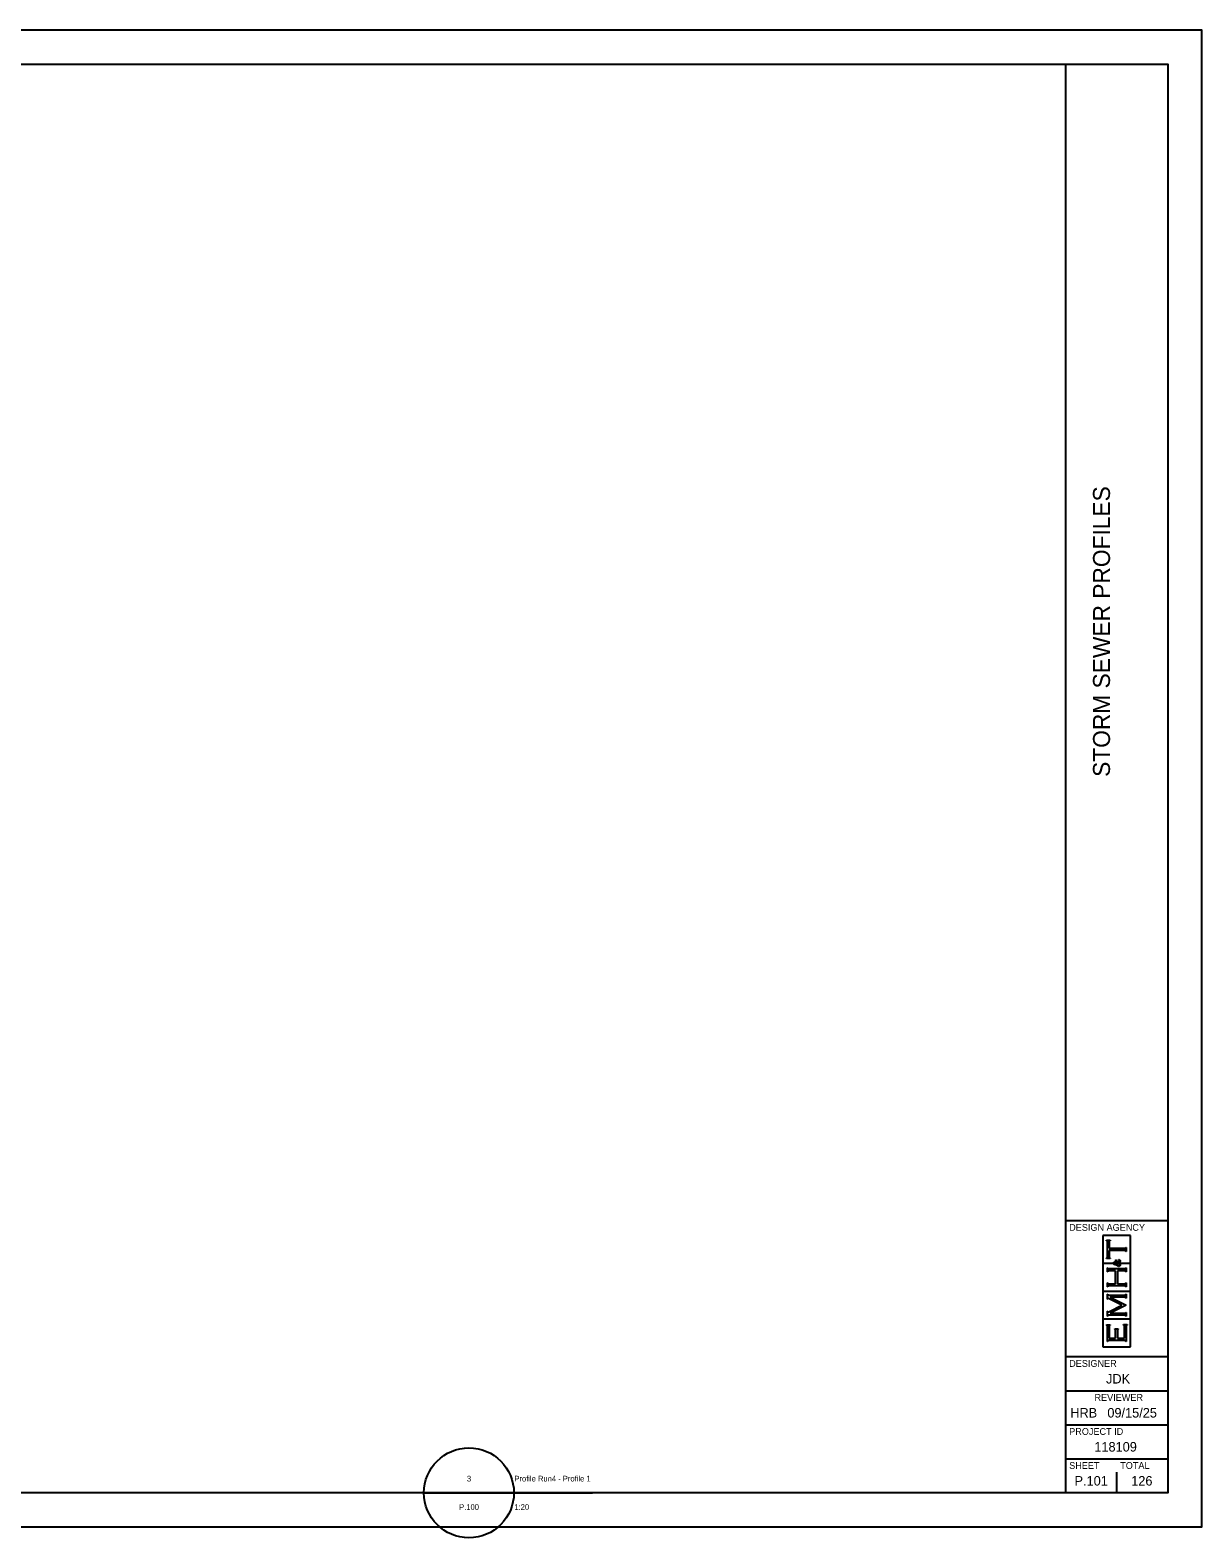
# Model space of a CAD drawing. Extents: x -0.4 to 34, y -0.2 to 22.
# Drawn here: x 16.78 to 34, y -0.16 to 22 of the extents above; entities that cross this region are included whole.
import ezdxf

# ---------------------------------------------------------------- set-up
doc = ezdxf.new("R2010")
doc.units = 0
for name, color, linetype in [('_CIVIL_CONSTRUCTION', 7, 'Continuous'), ('GE_P_Alignment', 7, 'Continuous'), ('PF_X_Ground_Line', 7, 'Continuous'), ('SC_Scratch1', 7, 'Continuous')]:
    doc.layers.add(name, color=color, linetype=linetype)

msp = doc.modelspace()

# ---------------------------------------------------------------- linework, layer by layer
at = {"layer": '_CIVIL_CONSTRUCTION'}
for p, q in [((32, 0.5), (32, 21.5)), ((32, 4.5), (33.5, 4.5)), ((32, 2.5), (33.5, 2.5)), ((32, 2), (33.5, 2)), ((32, 1.5), (33.5, 1.5)), ((32, 1), (33.5, 1))]:
    msp.add_line(p, q, dxfattribs=at)
msp.add_lwpolyline([(1.5, 21.5), (33.5, 21.5), (33.5, 0.5), (1.5, 0.5)], close=True, dxfattribs=at)
at = {"layer": 'GE_P_Alignment'}
msp.add_lwpolyline([(0, 0), (34, 0), (34, 22), (0, 22)], close=True, dxfattribs=at)
at = {"layer": 'PF_X_Ground_Line'}
for p, q in [((32.952, 4.279), (32.547, 4.279)), ((32.547, 4.279), (32.547, 3.875)), ((32.952, 3.875), (32.952, 4.279)), ((32.598, 4.204), (32.598, 4.211)), ((32.598, 4.211), (32.65, 4.211)), ((32.603, 4.203), (32.598, 4.204)), ((32.606, 4.201), (32.603, 4.203)), ((32.608, 4.199), (32.606, 4.201)), ((32.61, 4.196), (32.608, 4.199)), ((32.611, 4.192), (32.61, 4.196)), ((32.611, 4.187), (32.611, 4.192)), ((32.611, 3.968), (32.611, 4.187)), ((32.638, 4.196), (32.637, 4.192)), ((32.637, 4.192), (32.637, 4.187)), ((32.637, 4.187), (32.637, 4.093)), ((32.637, 4.093), (32.864, 4.093)), ((32.864, 4.061), (32.637, 4.061)), ((32.637, 4.061), (32.637, 3.968)), ((32.64, 4.199), (32.638, 4.196)), ((32.642, 4.201), (32.64, 4.199)), ((32.645, 4.203), (32.642, 4.201)), ((32.65, 4.204), (32.645, 4.203)), ((32.65, 4.211), (32.65, 4.204)), ((32.864, 4.093), (32.869, 4.093)), ((32.87, 4.061), (32.864, 4.061)), ((32.869, 4.093), (32.873, 4.094)), ((32.874, 4.06), (32.87, 4.061)), ((32.873, 4.094), (32.876, 4.096)), ((32.876, 4.059), (32.874, 4.06)), ((32.876, 4.096), (32.878, 4.097)), ((32.878, 4.057), (32.876, 4.059)), ((32.878, 4.097), (32.88, 4.101)), ((32.88, 4.053), (32.878, 4.057)), ((32.88, 4.101), (32.881, 4.106)), ((32.881, 4.048), (32.88, 4.053)), ((32.881, 4.106), (32.888, 4.106)), ((32.888, 4.048), (32.881, 4.048)), ((32.888, 4.106), (32.888, 4.048)), ((32.547, 3.875), (32.696, 3.875)), ((32.696, 3.869), (32.547, 3.869)), ((32.547, 3.869), (32.547, 3.465)), ((32.598, 3.95), (32.603, 3.951)), ((32.598, 3.944), (32.598, 3.95)), ((32.65, 3.944), (32.598, 3.944)), ((32.603, 3.951), (32.606, 3.953)), ((32.606, 3.953), (32.608, 3.955)), ((32.608, 3.955), (32.61, 3.958)), ((32.61, 3.958), (32.611, 3.962)), ((32.611, 3.962), (32.611, 3.968)), ((32.611, 3.749), (32.611, 3.807)), ((32.611, 3.807), (32.617, 3.807)), ((32.617, 3.807), (32.619, 3.802)), ((32.619, 3.802), (32.62, 3.798)), ((32.62, 3.798), (32.623, 3.797)), ((32.623, 3.797), (32.625, 3.795)), ((32.625, 3.795), (32.629, 3.794)), ((32.629, 3.794), (32.635, 3.794)), ((32.635, 3.794), (32.864, 3.794)), ((32.637, 3.968), (32.637, 3.962)), ((32.637, 3.962), (32.638, 3.958)), ((32.638, 3.958), (32.64, 3.955)), ((32.64, 3.955), (32.642, 3.953)), ((32.642, 3.953), (32.645, 3.951)), ((32.645, 3.951), (32.65, 3.95)), ((32.65, 3.95), (32.65, 3.944)), ((32.696, 3.875), (32.696, 3.869)), ((32.703, 3.879), (32.705, 3.883)), ((32.703, 3.873), (32.703, 3.879)), ((32.703, 3.868), (32.703, 3.873)), ((32.705, 3.863), (32.703, 3.868)), ((32.705, 3.883), (32.708, 3.887)), ((32.708, 3.858), (32.705, 3.863)), ((32.708, 3.887), (32.711, 3.89)), ((32.709, 3.879), (32.708, 3.876)), ((32.708, 3.876), (32.708, 3.873)), ((32.708, 3.873), (32.708, 3.869)), ((32.708, 3.869), (32.71, 3.866)), ((32.712, 3.853), (32.708, 3.858)), ((32.712, 3.881), (32.709, 3.879)), ((32.71, 3.866), (32.712, 3.864)), ((32.711, 3.89), (32.715, 3.892)), ((32.714, 3.883), (32.712, 3.881)), ((32.712, 3.864), (32.715, 3.862)), ((32.718, 3.85), (32.712, 3.853)), ((32.716, 3.884), (32.714, 3.883)), ((32.715, 3.892), (32.72, 3.892)), ((32.715, 3.862), (32.718, 3.861)), ((32.72, 3.884), (32.716, 3.884)), ((32.718, 3.861), (32.721, 3.861)), ((32.726, 3.85), (32.718, 3.85)), ((32.72, 3.892), (32.725, 3.892)), ((32.724, 3.884), (32.72, 3.884)), ((32.721, 3.861), (32.723, 3.861)), ((32.723, 3.861), (32.725, 3.862)), ((32.728, 3.882), (32.724, 3.884)), ((32.725, 3.892), (32.729, 3.89)), ((32.725, 3.862), (32.728, 3.862)), ((32.729, 3.85), (32.726, 3.85)), ((32.731, 3.88), (32.728, 3.882)), ((32.728, 3.862), (32.731, 3.863)), ((32.729, 3.89), (32.732, 3.887)), ((32.731, 3.85), (32.729, 3.85)), ((32.734, 3.877), (32.731, 3.88)), ((32.731, 3.863), (32.735, 3.865)), ((32.734, 3.851), (32.731, 3.85)), ((32.732, 3.887), (32.736, 3.883)), ((32.737, 3.872), (32.734, 3.877)), ((32.737, 3.852), (32.734, 3.851)), ((32.735, 3.865), (32.74, 3.867)), ((32.736, 3.883), (32.74, 3.878)), ((32.74, 3.867), (32.737, 3.872)), ((32.741, 3.853), (32.737, 3.852)), ((32.738, 3.893), (32.738, 3.922)), ((32.738, 3.922), (32.741, 3.922)), ((32.741, 3.893), (32.738, 3.893)), ((32.74, 3.878), (32.744, 3.869)), ((32.741, 3.922), (32.741, 3.918)), ((32.741, 3.918), (32.742, 3.915)), ((32.742, 3.896), (32.741, 3.895)), ((32.741, 3.895), (32.741, 3.893)), ((32.746, 3.855), (32.741, 3.853)), ((32.742, 3.915), (32.743, 3.913)), ((32.743, 3.897), (32.742, 3.896)), ((32.743, 3.913), (32.745, 3.911)), ((32.745, 3.899), (32.743, 3.897)), ((32.744, 3.869), (32.754, 3.875)), ((32.745, 3.911), (32.749, 3.908)), ((32.746, 3.899), (32.745, 3.899)), ((32.748, 3.899), (32.746, 3.899)), ((32.752, 3.844), (32.746, 3.855)), ((32.755, 3.899), (32.748, 3.899)), ((32.749, 3.908), (32.756, 3.904)), ((32.756, 3.86), (32.751, 3.857)), ((32.751, 3.857), (32.754, 3.852)), ((32.757, 3.837), (32.752, 3.844)), ((32.754, 3.875), (32.764, 3.881)), ((32.754, 3.852), (32.757, 3.848)), ((32.763, 3.895), (32.755, 3.899)), ((32.756, 3.904), (32.763, 3.9)), ((32.761, 3.863), (32.756, 3.86)), ((32.757, 3.848), (32.761, 3.845)), ((32.763, 3.833), (32.757, 3.837)), ((32.764, 3.865), (32.761, 3.863)), ((32.761, 3.845), (32.765, 3.843)), ((32.763, 3.9), (32.77, 3.896)), ((32.772, 3.887), (32.763, 3.895)), ((32.768, 3.829), (32.763, 3.833)), ((32.764, 3.881), (32.772, 3.887)), ((32.768, 3.867), (32.764, 3.865)), ((32.765, 3.843), (32.769, 3.841)), ((32.774, 3.872), (32.768, 3.867)), ((32.774, 3.827), (32.768, 3.829)), ((32.769, 3.841), (32.773, 3.841)), ((32.77, 3.896), (32.776, 3.891)), ((32.773, 3.841), (32.778, 3.841)), ((32.782, 3.878), (32.774, 3.872)), ((32.779, 3.827), (32.774, 3.827)), ((32.776, 3.891), (32.781, 3.895)), ((32.778, 3.841), (32.782, 3.843)), ((32.779, 3.923), (32.781, 3.926)), ((32.782, 3.922), (32.779, 3.923)), ((32.785, 3.827), (32.779, 3.827)), ((32.781, 3.926), (32.787, 3.924)), ((32.781, 3.895), (32.784, 3.898)), ((32.785, 3.921), (32.782, 3.922)), ((32.786, 3.873), (32.782, 3.878)), ((32.782, 3.843), (32.786, 3.846)), ((32.784, 3.898), (32.786, 3.901)), ((32.786, 3.919), (32.785, 3.921)), ((32.79, 3.829), (32.785, 3.827)), ((32.788, 3.917), (32.786, 3.919)), ((32.786, 3.901), (32.788, 3.904)), ((32.791, 3.886), (32.786, 3.881)), ((32.786, 3.881), (32.791, 3.876)), ((32.788, 3.869), (32.786, 3.873)), ((32.786, 3.846), (32.789, 3.849)), ((32.787, 3.924), (32.792, 3.921)), ((32.789, 3.914), (32.788, 3.917)), ((32.788, 3.904), (32.789, 3.908)), ((32.79, 3.867), (32.788, 3.869)), ((32.789, 3.911), (32.789, 3.914)), ((32.789, 3.908), (32.789, 3.911)), ((32.789, 3.849), (32.791, 3.853)), ((32.791, 3.864), (32.79, 3.867)), ((32.793, 3.834), (32.79, 3.829)), ((32.794, 3.89), (32.791, 3.886)), ((32.791, 3.876), (32.795, 3.87)), ((32.791, 3.861), (32.791, 3.864)), ((32.791, 3.859), (32.791, 3.861)), ((32.791, 3.853), (32.791, 3.859)), ((32.792, 3.921), (32.795, 3.918)), ((32.797, 3.838), (32.793, 3.834)), ((32.796, 3.894), (32.794, 3.89)), ((32.795, 3.918), (32.798, 3.914)), ((32.795, 3.87), (32.797, 3.866)), ((32.798, 3.897), (32.796, 3.894)), ((32.797, 3.866), (32.798, 3.861)), ((32.799, 3.844), (32.797, 3.838)), ((32.798, 3.914), (32.799, 3.91)), ((32.799, 3.901), (32.798, 3.897)), ((32.798, 3.861), (32.799, 3.857)), ((32.799, 3.91), (32.799, 3.905)), ((32.799, 3.905), (32.799, 3.901)), ((32.803, 3.869), (32.799, 3.875)), ((32.799, 3.875), (32.952, 3.875)), ((32.799, 3.857), (32.799, 3.852)), ((32.799, 3.852), (32.799, 3.844)), ((32.952, 3.869), (32.803, 3.869)), ((32.864, 3.794), (32.869, 3.794)), ((32.869, 3.794), (32.873, 3.795)), ((32.873, 3.795), (32.876, 3.797)), ((32.876, 3.797), (32.878, 3.798)), ((32.878, 3.798), (32.88, 3.802)), ((32.88, 3.802), (32.881, 3.807)), ((32.881, 3.807), (32.888, 3.807)), ((32.888, 3.807), (32.888, 3.749)), ((32.952, 3.465), (32.952, 3.869)), ((32.617, 3.749), (32.611, 3.749)), ((32.611, 3.527), (32.611, 3.585)), ((32.611, 3.585), (32.617, 3.585)), ((32.618, 3.754), (32.617, 3.749)), ((32.617, 3.585), (32.619, 3.58)), ((32.62, 3.758), (32.618, 3.754)), ((32.619, 3.58), (32.62, 3.576)), ((32.623, 3.76), (32.62, 3.758)), ((32.62, 3.576), (32.623, 3.574)), ((32.625, 3.761), (32.623, 3.76)), ((32.623, 3.574), (32.625, 3.573)), ((32.629, 3.762), (32.625, 3.761)), ((32.625, 3.573), (32.629, 3.572)), ((32.635, 3.762), (32.629, 3.762)), ((32.629, 3.572), (32.635, 3.572)), ((32.732, 3.762), (32.635, 3.762)), ((32.635, 3.572), (32.732, 3.572)), ((32.732, 3.572), (32.732, 3.762)), ((32.864, 3.762), (32.759, 3.762)), ((32.759, 3.762), (32.759, 3.572)), ((32.759, 3.572), (32.864, 3.572)), ((32.87, 3.762), (32.864, 3.762)), ((32.864, 3.572), (32.87, 3.572)), ((32.874, 3.761), (32.87, 3.762)), ((32.87, 3.572), (32.874, 3.573)), ((32.876, 3.76), (32.874, 3.761)), ((32.874, 3.573), (32.876, 3.574)), ((32.878, 3.758), (32.876, 3.76)), ((32.876, 3.574), (32.878, 3.576)), ((32.88, 3.754), (32.878, 3.758)), ((32.878, 3.576), (32.88, 3.58)), ((32.881, 3.749), (32.88, 3.754)), ((32.88, 3.58), (32.881, 3.585)), ((32.888, 3.749), (32.881, 3.749)), ((32.881, 3.585), (32.888, 3.585)), ((32.888, 3.585), (32.888, 3.527)), ((32.547, 3.465), (32.952, 3.465)), ((32.952, 3.459), (32.547, 3.459)), ((32.547, 3.459), (32.547, 3.055)), ((32.617, 3.527), (32.611, 3.527)), ((32.611, 3.345), (32.611, 3.418)), ((32.611, 3.418), (32.617, 3.418)), ((32.617, 3.345), (32.611, 3.345)), ((32.618, 3.532), (32.617, 3.527)), ((32.617, 3.418), (32.619, 3.412)), ((32.62, 3.352), (32.617, 3.345)), ((32.62, 3.536), (32.618, 3.532)), ((32.619, 3.412), (32.62, 3.409)), ((32.623, 3.537), (32.62, 3.536)), ((32.62, 3.409), (32.623, 3.407)), ((32.622, 3.355), (32.62, 3.352)), ((32.626, 3.355), (32.622, 3.355)), ((32.625, 3.539), (32.623, 3.537)), ((32.623, 3.407), (32.625, 3.405)), ((32.629, 3.54), (32.625, 3.539)), ((32.625, 3.405), (32.629, 3.405)), ((32.629, 3.355), (32.626, 3.355)), ((32.635, 3.54), (32.629, 3.54)), ((32.629, 3.405), (32.635, 3.405)), ((32.633, 3.353), (32.629, 3.355)), ((32.64, 3.35), (32.633, 3.353)), ((32.864, 3.54), (32.635, 3.54)), ((32.635, 3.405), (32.864, 3.405)), ((32.825, 3.257), (32.64, 3.35)), ((32.864, 3.373), (32.654, 3.373)), ((32.654, 3.373), (32.888, 3.255)), ((32.75, 3.5), (32.75, 3.5)), ((32.87, 3.54), (32.864, 3.54)), ((32.864, 3.405), (32.869, 3.405)), ((32.87, 3.373), (32.864, 3.373)), ((32.869, 3.405), (32.873, 3.405)), ((32.874, 3.539), (32.87, 3.54)), ((32.874, 3.372), (32.87, 3.373)), ((32.873, 3.405), (32.876, 3.407)), ((32.876, 3.538), (32.874, 3.539)), ((32.876, 3.37), (32.874, 3.372)), ((32.878, 3.536), (32.876, 3.538)), ((32.876, 3.407), (32.878, 3.409)), ((32.878, 3.369), (32.876, 3.37)), ((32.88, 3.532), (32.878, 3.536)), ((32.878, 3.409), (32.88, 3.412)), ((32.88, 3.365), (32.878, 3.369)), ((32.881, 3.527), (32.88, 3.532)), ((32.88, 3.412), (32.881, 3.418)), ((32.881, 3.36), (32.88, 3.365)), ((32.888, 3.527), (32.881, 3.527)), ((32.881, 3.418), (32.888, 3.418)), ((32.888, 3.36), (32.881, 3.36)), ((32.888, 3.418), (32.888, 3.36)), ((32.952, 3.055), (32.952, 3.459)), ((32.611, 3.096), (32.611, 3.168)), ((32.611, 3.168), (32.617, 3.168)), ((32.617, 3.168), (32.62, 3.162)), ((32.62, 3.105), (32.618, 3.102)), ((32.62, 3.162), (32.622, 3.158)), ((32.623, 3.107), (32.62, 3.105)), ((32.622, 3.158), (32.626, 3.158)), ((32.625, 3.109), (32.623, 3.107)), ((32.629, 3.109), (32.625, 3.109)), ((32.626, 3.158), (32.627, 3.158)), ((32.627, 3.158), (32.633, 3.161)), ((32.635, 3.109), (32.629, 3.109)), ((32.633, 3.161), (32.641, 3.165)), ((32.864, 3.109), (32.635, 3.109)), ((32.641, 3.165), (32.825, 3.257)), ((32.888, 3.255), (32.654, 3.138)), ((32.654, 3.138), (32.864, 3.138)), ((32.864, 3.138), (32.869, 3.138)), ((32.87, 3.109), (32.864, 3.109)), ((32.869, 3.138), (32.873, 3.139)), ((32.874, 3.109), (32.87, 3.109)), ((32.873, 3.139), (32.876, 3.141)), ((32.876, 3.107), (32.874, 3.109)), ((32.876, 3.141), (32.878, 3.143)), ((32.878, 3.105), (32.876, 3.107)), ((32.878, 3.143), (32.88, 3.146)), ((32.88, 3.102), (32.878, 3.105)), ((32.88, 3.146), (32.881, 3.151)), ((32.881, 3.151), (32.888, 3.151)), ((32.888, 3.151), (32.888, 3.096)), ((32.547, 3.055), (32.952, 3.055)), ((32.952, 3.049), (32.547, 3.049)), ((32.547, 3.049), (32.547, 2.645)), ((32.598, 2.962), (32.598, 2.969)), ((32.598, 2.969), (32.65, 2.969)), ((32.603, 2.961), (32.598, 2.962)), ((32.606, 2.959), (32.603, 2.961)), ((32.608, 2.957), (32.606, 2.959)), ((32.61, 2.955), (32.608, 2.957)), ((32.611, 2.951), (32.61, 2.955)), ((32.617, 3.096), (32.611, 3.096)), ((32.611, 2.945), (32.611, 2.951)), ((32.611, 2.725), (32.611, 2.945)), ((32.618, 3.102), (32.617, 3.096)), ((32.64, 2.957), (32.638, 2.955)), ((32.638, 2.955), (32.638, 2.951)), ((32.638, 2.951), (32.638, 2.945)), ((32.638, 2.945), (32.638, 2.77)), ((32.642, 2.959), (32.64, 2.957)), ((32.645, 2.961), (32.642, 2.959)), ((32.65, 2.962), (32.645, 2.961)), ((32.65, 2.969), (32.65, 2.962)), ((32.719, 2.902), (32.719, 2.908)), ((32.719, 2.908), (32.772, 2.908)), ((32.724, 2.901), (32.719, 2.902)), ((32.728, 2.899), (32.724, 2.901)), ((32.729, 2.896), (32.728, 2.899)), ((32.731, 2.894), (32.729, 2.896)), ((32.732, 2.89), (32.731, 2.894)), ((32.732, 2.884), (32.732, 2.89)), ((32.732, 2.77), (32.732, 2.884)), ((32.76, 2.894), (32.759, 2.89)), ((32.759, 2.89), (32.759, 2.884)), ((32.759, 2.884), (32.759, 2.77)), ((32.761, 2.896), (32.76, 2.894)), ((32.763, 2.899), (32.761, 2.896)), ((32.767, 2.901), (32.763, 2.899)), ((32.772, 2.902), (32.767, 2.901)), ((32.772, 2.908), (32.772, 2.902)), ((32.848, 2.965), (32.848, 2.972)), ((32.848, 2.972), (32.901, 2.972)), ((32.853, 2.964), (32.848, 2.965)), ((32.857, 2.962), (32.853, 2.964)), ((32.859, 2.96), (32.857, 2.962)), ((32.86, 2.958), (32.859, 2.96)), ((32.861, 2.953), (32.86, 2.958)), ((32.861, 2.948), (32.861, 2.953)), ((32.861, 2.77), (32.861, 2.948)), ((32.881, 3.096), (32.88, 3.102)), ((32.888, 3.096), (32.881, 3.096)), ((32.889, 2.957), (32.888, 2.953)), ((32.888, 2.953), (32.888, 2.948)), ((32.888, 2.948), (32.888, 2.725)), ((32.891, 2.96), (32.889, 2.957)), ((32.892, 2.962), (32.891, 2.96)), ((32.896, 2.964), (32.892, 2.962)), ((32.901, 2.965), (32.896, 2.964)), ((32.901, 2.972), (32.901, 2.965)), ((32.952, 2.645), (32.952, 3.049)), ((32.617, 2.725), (32.611, 2.725)), ((32.619, 2.73), (32.617, 2.725)), ((32.62, 2.734), (32.619, 2.73)), ((32.623, 2.735), (32.62, 2.734)), ((32.625, 2.737), (32.623, 2.735)), ((32.629, 2.738), (32.625, 2.737)), ((32.635, 2.738), (32.629, 2.738)), ((32.864, 2.738), (32.635, 2.738)), ((32.638, 2.77), (32.732, 2.77)), ((32.759, 2.77), (32.861, 2.77)), ((32.87, 2.738), (32.864, 2.738)), ((32.874, 2.737), (32.87, 2.738)), ((32.876, 2.735), (32.874, 2.737)), ((32.878, 2.734), (32.876, 2.735)), ((32.88, 2.73), (32.878, 2.734)), ((32.881, 2.725), (32.88, 2.73)), ((32.888, 2.725), (32.881, 2.725)), ((32.547, 2.645), (32.952, 2.645)), ((32.375, 0.675), (32.375, 0.675)), ((32.75, 0.5), (32.75, 0.8))]:
    msp.add_line(p, q, dxfattribs=at)
at = {"layer": 'SC_Scratch1'}
for p, q in [((22.565, 0.498), (23.888, 0.498)), ((23.232, 0.498), (25.044, 0.498))]:
    msp.add_line(p, q, dxfattribs=at)
msp.add_circle((23.227, 0.498), 0.661, dxfattribs=at)

# ---------------------------------------------------------------- texts
at = {"layer": 'PF_X_Ground_Line'}
msp.add_text('STORM SEWER PROFILES', height=0.25, rotation=90, dxfattribs=at).set_placement((32.65, 11.023))
for s, height, p in [('DESIGN AGENCY', 0.1, (32.05, 4.35)), ('DESIGNER', 0.1, (32.05, 2.35)), ('JDK', 0.14, (32.592, 2.105)), ('REVIEWER', 0.1, (32.422, 1.85)), ('HRB', 0.14, (32.066, 1.605)), ('09/15/25', 0.14, (32.611, 1.605)), ('PROJECT ID', 0.1, (32.05, 1.35)), ('118109', 0.14, (32.42, 1.105)), ('SHEET', 0.1, (32.05, 0.85)), ('TOTAL', 0.1, (32.8, 0.85)), ('P.101', 0.14, (32.129, 0.605)), ('126', 0.14, (32.962, 0.605))]:
    msp.add_text(s, height=height, dxfattribs=at).set_placement(p)
at = {"layer": 'SC_Scratch1'}
for s, height, p in [('3', 0.0833, (23.197, 0.665)), ('Profile Run4 - Profile 1', 0.08333, (23.895, 0.665)), ('P.100', 0.0833, (23.083, 0.248)), ('1:20', 0.0833, (23.895, 0.248))]:
    msp.add_text(s, height=height, dxfattribs=at).set_placement(p)

doc.saveas('drawing.dxf')
